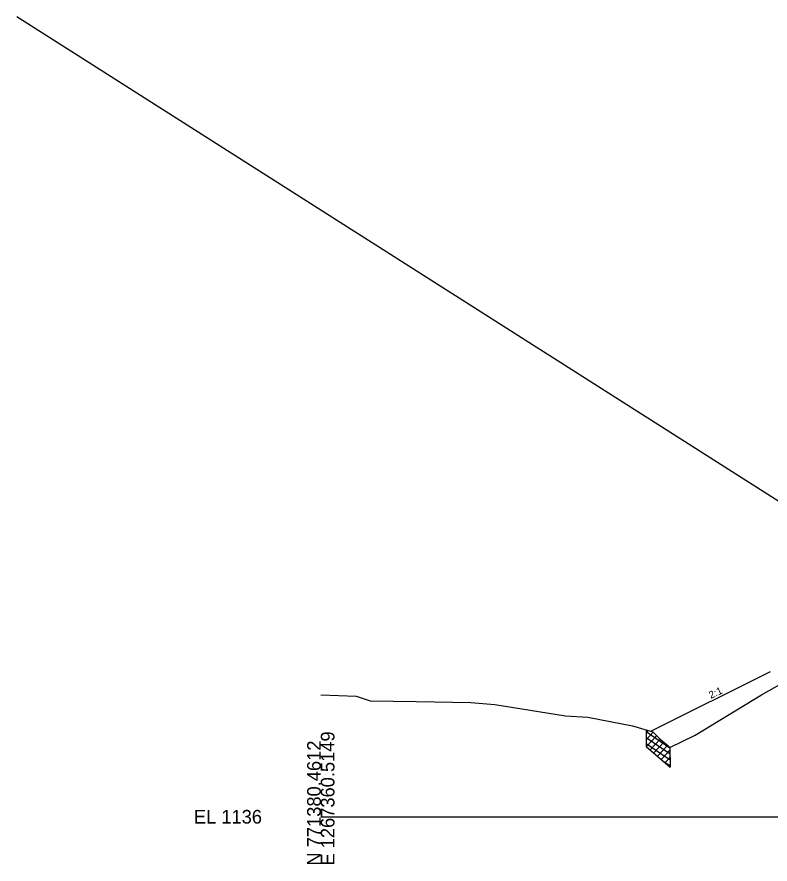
# Model space of a CAD drawing. Extents: x -3833 to 1267678, y -522 to 773248.
# Drawn here: x -62.2 to 92, y 8490.3 to 8663.9 of the extents above; entities that cross this region are included whole.
import ezdxf

# ---------------------------------------------------------------- set-up
doc = ezdxf.new("R2010")
doc.units = 0
for name, color, linetype in [('Exist Cross Section Cell', 7, 'Continuous'), ('Exist XS Ground Line', 7, 'Continuous'), ('Prop CMT DNC', 7, 'Continuous'), ('Prop XS Finish Grade', 7, 'Continuous'), ('Prop XS Label Text', 7, 'Continuous'), ('Prop XS Undercut Exc', 7, 'Continuous'), ('Scratch_Level_1', 7, 'Continuous')]:
    doc.layers.add(name, color=color, linetype=linetype)

msp = doc.modelspace()

# ---------------------------------------------------------------- linework, layer by layer
at = {"layer": 'Exist Cross Section Cell'}
msp.add_line((0, 8500), (150, 8500), dxfattribs=at)
at = {"layer": 'Exist XS Ground Line'}
for p, q in [((90.31, 8525), (97.19, 8528.92)), ((0, 8525), (7.22, 8524.71)), ((76.7, 8516.71), (90.31, 8525)), ((7.22, 8524.71), (10.09, 8523.76)), ((10.09, 8523.76), (19.56, 8523.64)), ((19.56, 8523.64), (30.74, 8523.41)), ((30.74, 8523.41), (35.67, 8523.01)), ((35.67, 8523.01), (50.15, 8520.64)), ((50.15, 8520.64), (54.69, 8520.37)), ((54.69, 8520.37), (63.86, 8518.6)), ((63.86, 8518.6), (68.02, 8517.4)), ((68.02, 8517.4), (69.52, 8515.91)), ((71.51, 8514.2), (76.7, 8516.71)), ((69.52, 8515.91), (71.06, 8514.59)), ((71.06, 8514.59), (71.51, 8514.2))]:
    msp.add_line(p, q, dxfattribs=at)
at = {"layer": 'Prop XS Finish Grade'}
msp.add_line((92.03, 8529.71), (67.65, 8517.51), dxfattribs=at)
at = {"layer": 'Prop XS Undercut Exc'}
for p, q in [((66.65, 8517.8), (66.65, 8514.42)), ((67.07, 8517.68), (66.65, 8517.22)), ((66.65, 8517.46), (71.51, 8514.11)), ((68.1, 8517.33), (66.65, 8515.75)), ((66.65, 8516.24), (71.54, 8512.87)), ((68.81, 8516.62), (66.72, 8514.36)), ((66.65, 8515.03), (71.56, 8511.64)), ((66.65, 8514.42), (71.59, 8510.18)), ((69.52, 8515.91), (67.48, 8513.71)), ((70.28, 8515.26), (68.24, 8513.06)), ((71.04, 8514.61), (69, 8512.4)), ((71.52, 8513.66), (69.76, 8511.75)), ((71.51, 8514.2), (71.59, 8510.18)), ((70.24, 8511.34), (71.59, 8510.41)), ((71.55, 8512.22), (70.52, 8511.1)), ((71.58, 8510.78), (71.27, 8510.45))]:
    msp.add_line(p, q, dxfattribs=at)
at = {"layer": 'Scratch_Level_1'}
msp.add_line((150, 8528.8), (-62.25, 8663.86), dxfattribs=at)

# ---------------------------------------------------------------- texts
at = {"layer": 'Exist Cross Section Cell'}
for s, p in [('E 1267360.5149', (2.8, 8490)), ('N 771380.4612', (0, 8490))]:
    msp.add_text(s, height=2.8, rotation=90, dxfattribs=at).set_placement(p)
msp.add_text('EL 1136', height=2.8, dxfattribs=at).set_placement((-26, 8498.6))
at = {"layer": 'Prop CMT DNC'}
msp.add_text('X', height=0.00025, dxfattribs=at).set_placement((66.45, 8517.85))
at = {"layer": 'Prop XS Label Text'}
msp.add_text('2:1', height=1.5, rotation=24.9367, dxfattribs=at).set_placement((79.91, 8524.14))

doc.saveas('drawing.dxf')
